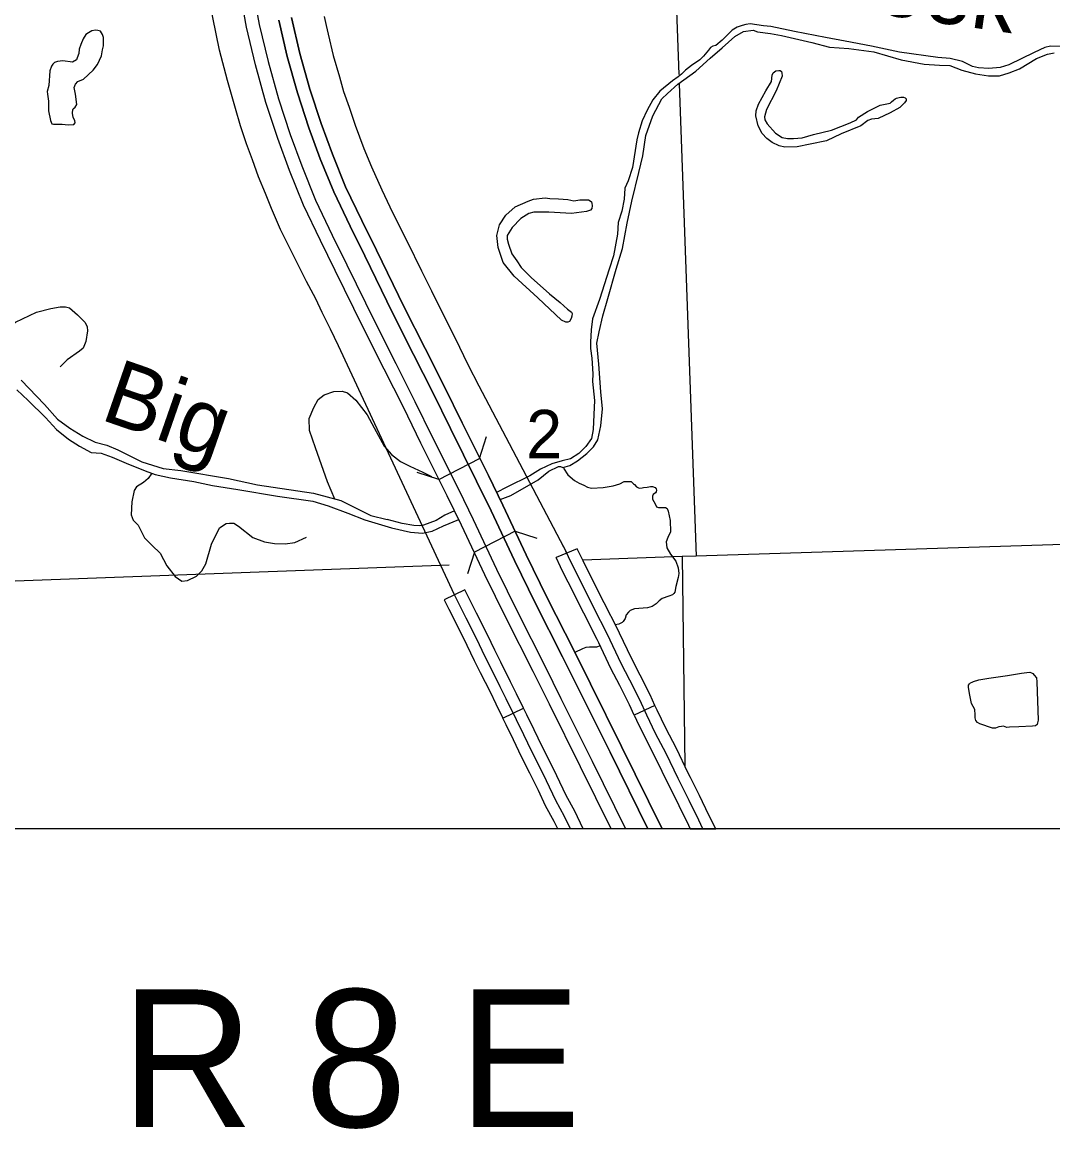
# Model space of a CAD drawing. Extents: x -117616 to 64730, y 54117 to 789866.
# Drawn here: x 62911 to 63045.9, y 54350 to 54494.9 of the extents above; entities that cross this region are included whole.
import ezdxf

# ---------------------------------------------------------------- set-up
doc = ezdxf.new("R2010")
doc.units = 0
for name, color, linetype in [('19', 7, 'Continuous'), ('27', 7, 'Continuous'), ('35', 7, 'Continuous'), ('36', 7, 'Continuous'), ('4', 7, 'Continuous'), ('5', 7, 'Continuous'), ('9', 7, 'Continuous'), ('Default', 7, 'Continuous'), ('R_No Plot', 7, 'Continuous')]:
    doc.layers.add(name, color=color, linetype=linetype)

msp = doc.modelspace()

# ---------------------------------------------------------------- linework, layer by layer
at = {"layer": '19'}
for p, q in [((62940.38, 54494.27), (62939.42, 54499.38)), ((62941.1, 54499.66), (62942.04, 54494.62)), ((62946.25, 54495.51), (62947.35, 54490.82)), ((62941.54, 54489.33), (62940.38, 54494.27)), ((62942.04, 54494.62), (62943.19, 54489.75)), ((62945.71, 54490.4), (62944.58, 54495.16)), ((62943.19, 54489.75), (62944.54, 54484.88)), ((62947.03, 54485.64), (62945.71, 54490.4)), ((62947.35, 54490.82), (62948.66, 54486.13)), ((62942.91, 54484.39), (62941.54, 54489.33)), ((62948.53, 54481.08), (62947.03, 54485.64)), ((62948.66, 54486.13), (62950.13, 54481.64)), ((62944.47, 54479.67), (62942.91, 54484.39)), ((62944.54, 54484.88), (62946.07, 54480.22)), ((62950.02, 54477.03), (62948.53, 54481.08)), ((62950.13, 54481.64), (62951.61, 54477.64)), ((62946.01, 54475.48), (62944.47, 54479.67)), ((62946.07, 54480.22), (62947.6, 54476.09)), ((62951.79, 54472.68), (62950.02, 54477.03)), ((62951.61, 54477.64), (62953.34, 54473.37)), ((62947.85, 54470.95), (62946.01, 54475.48)), ((62947.6, 54476.09), (62949.41, 54471.63)), ((62953.93, 54468.19), (62951.79, 54472.68)), ((62953.34, 54473.37), (62955.46, 54468.93)), ((62950.06, 54466.31), (62947.85, 54470.95)), ((62949.41, 54471.63), (62951.59, 54467.05)), ((62955.85, 54464.31), (62953.93, 54468.19)), ((62955.46, 54468.93), (62957.38, 54465.06)), ((62951.59, 54467.05), (62953.52, 54463.16)), ((62951.99, 54462.41), (62950.06, 54466.31)), ((62957.38, 54465.06), (62961.02, 54457.6)), ((62959.49, 54456.85), (62955.85, 54464.31)), ((62955.64, 54454.93), (62951.99, 54462.41)), ((62953.52, 54463.16), (62957.17, 54455.69)), ((62962.24, 54451.42), (62959.49, 54456.85)), ((62961.02, 54457.6), (62963.76, 54452.19)), ((62958.4, 54449.48), (62955.64, 54454.93)), ((62957.17, 54455.69), (62959.92, 54450.25)), ((62963.76, 54452.19), (62966.28, 54447.18)), ((62964.75, 54446.42), (62962.24, 54451.42)), ((62960.9, 54444.51), (62958.4, 54449.48)), ((62959.92, 54450.25), (62962.42, 54445.27)), ((62967.06, 54441.71), (62964.75, 54446.42)), ((62966.28, 54447.18), (62968.58, 54442.46)), ((62962.42, 54445.27), (62964.72, 54440.56)), ((62963.2, 54439.81), (62960.9, 54444.51)), ((62968.58, 54442.46), (62972.02, 54435.58)), ((62964.72, 54440.56), (62968.16, 54433.68)), ((62970.49, 54434.83), (62967.06, 54441.71)), ((62966.64, 54432.93), (62963.2, 54439.81)), ((62972.39, 54430.93), (62970.49, 54434.83)), ((62972.02, 54435.58), (62973.92, 54431.67)), ((62968.16, 54433.68), (62970.04, 54429.81)), ((62968.51, 54429.08), (62966.64, 54432.93)), ((62975.45, 54424.43), (62972.39, 54430.93)), ((62973.92, 54431.67), (62976.98, 54425.17)), ((62971.57, 54422.57), (62968.51, 54429.08)), ((62970.04, 54429.81), (62973.1, 54423.31)), ((62976.98, 54425.17), (62979.71, 54419.57)), ((62973.1, 54423.31), (62975.86, 54417.65)), ((62978.19, 54418.81), (62975.45, 54424.43)), ((62974.34, 54416.89), (62971.57, 54422.57)), ((62981.73, 54411.83), (62978.19, 54418.81)), ((62979.71, 54419.57), (62983.24, 54412.6)), ((62975.86, 54417.65), (62979.4, 54410.66)), ((62977.88, 54409.9), (62974.34, 54416.89)), ((62983.86, 54407.56), (62981.73, 54411.83)), ((62983.24, 54412.6), (62985.38, 54408.32)), ((62979.4, 54410.66), (62981.53, 54406.4)), ((62980.01, 54405.64), (62977.88, 54409.9)), ((62987.95, 54399.34), (62983.86, 54407.56)), ((62985.38, 54408.32), (62989.47, 54400.09)), ((62984.1, 54397.43), (62980.01, 54405.64)), ((62981.53, 54406.4), (62985.62, 54398.19)), ((62989.47, 54400.09), (62994.78, 54389.3)), ((62992.89, 54389.3), (62987.95, 54399.34)), ((62988.1, 54389.3), (62984.1, 54397.43)), ((62985.62, 54398.19), (62989.99, 54389.3)), ((62989.99, 54389.3), (62988.1, 54389.3)), ((62994.78, 54389.3), (62992.89, 54389.3))]:
    msp.add_line(p, q, dxfattribs=at)
for points in [[(62994.78, 54389.3), (62989.47, 54400.09), (62985.38, 54408.32), (62983.24, 54412.6), (62979.71, 54419.57), (62976.98, 54425.17), (62973.92, 54431.67), (62972.02, 54435.58), (62968.58, 54442.46), (62966.28, 54447.18), (62963.76, 54452.19), (62961.02, 54457.6), (62957.38, 54465.06), (62955.46, 54468.93), (62953.34, 54473.37), (62951.61, 54477.64), (62950.13, 54481.64), (62948.66, 54486.13), (62947.35, 54490.82), (62946.25, 54495.51)], [(62944.58, 54495.16), (62945.71, 54490.4), (62947.03, 54485.64), (62948.53, 54481.08), (62950.02, 54477.03), (62951.79, 54472.68), (62953.93, 54468.19), (62955.85, 54464.31), (62959.49, 54456.85), (62962.24, 54451.42), (62964.75, 54446.42), (62967.06, 54441.71), (62970.49, 54434.83), (62972.39, 54430.93), (62975.45, 54424.43), (62978.19, 54418.81), (62981.73, 54411.83), (62983.86, 54407.56), (62987.95, 54399.34), (62992.89, 54389.3)]]:
    msp.add_lwpolyline(points, dxfattribs=at)
at = {"layer": '27'}
for p, q in [((62983.66, 54425.98), (62980.89, 54424.82)), ((62973.92, 54403.81), (62976.61, 54405.13)), ((62976.61, 54405.13), (62976.61, 54405.13)), ((62993.83, 54405.45), (62991.1, 54404.2)), ((62991.1, 54404.2), (62991.39, 54403.56)), ((62994.1, 54404.85), (62993.83, 54405.45)), ((62995.25, 54402.49), (62994.1, 54404.85)), ((62991.39, 54403.56), (62992.57, 54401.15)), ((62996.63, 54399.83), (62995.25, 54402.49)), ((62992.57, 54401.15), (62993.95, 54398.49)), ((62993.95, 54398.49), (62995.5, 54395.27)), ((62998.19, 54396.59), (62996.63, 54399.83)), ((62998.48, 54396.02), (62998.19, 54396.59)), ((62999.65, 54393.69), (62998.48, 54396.02)), ((62995.5, 54395.27), (62995.8, 54394.68)), ((62995.8, 54394.68), (62996.95, 54392.36)), ((63000.9, 54391.09), (62999.65, 54393.69)), ((62996.95, 54392.36), (62998.21, 54389.78)), ((62998.21, 54389.78), (62998.44, 54389.3)), ((63001.79, 54389.3), (63000.9, 54391.09)), ((62998.44, 54389.3), (63001.79, 54389.3))]:
    msp.add_line(p, q, dxfattribs=at)
for points in [[(62967.58, 54419.93), (62952.43, 54452.53), (62951.35, 54454.72), (62950.29, 54456.91), (62949.43, 54458.71), (62948.24, 54460.96), (62946.16, 54465.07), (62944.83, 54467.77), (62943.65, 54470.52), (62942.84, 54472.47), (62941.96, 54474.65), (62941.14, 54476.88), (62940.37, 54479), (62939.59, 54481.35), (62938.91, 54483.62), (62937.88, 54487.27), (62936.85, 54491.26), (62935.97, 54495.52), (62935.14, 54500.51), (62934.92, 54502.07), (62934.53, 54505.31), (62934.19, 54509.16), (62934.16, 54509.68)], [(62950.53, 54495.63), (62950.79, 54494.48), (62951.04, 54493.35), (62951.69, 54490.53), (62952.53, 54487.74), (62953.08, 54485.83), (62953.8, 54483.8), (62954.59, 54481.44), (62955.74, 54478.38), (62956.72, 54475.98), (62958.06, 54472.98), (62959.13, 54470.72), (62960.57, 54467.82), (62961.4, 54466.2), (62963.28, 54462.36), (62964.58, 54459.74), (62966.36, 54456.14), (62967.68, 54453.55), (62969.33, 54450.12), (62970.77, 54447.3), (62982.29, 54425.4)], [(63000.11, 54389.3), (62999.56, 54390.44), (62998.3, 54393.03), (62996.85, 54395.93), (62995.29, 54399.16), (62993.91, 54401.82), (62992.75, 54404.2), (62991.83, 54406.2), (62990.55, 54408.76), (62989.41, 54410.98), (62987.61, 54414.76), (62985.84, 54418.24), (62983.81, 54422.3), (62982.82, 54424.26), (62981.85, 54426.3)], [(62984.42, 54424.42), (62984.16, 54424.92), (62983.66, 54425.98)], [(62981.74, 54423.06), (62981.47, 54423.6), (62980.89, 54424.82)], [(62986.47, 54413.66), (62986.26, 54414.1), (62984.5, 54417.57), (62982.47, 54421.62), (62981.74, 54423.06)], [(62989.18, 54414.95), (62988.95, 54415.42), (62987.18, 54418.92), (62985.15, 54422.97), (62984.42, 54424.42)], [(62971.9, 54414.7), (62970.47, 54417.55), (62969.55, 54419.4), (62968.96, 54420.61), (62966.26, 54419.29)], [(62966.26, 54419.29), (62966.86, 54418.07), (62967.79, 54416.21), (62969.21, 54413.37)], [(62982.78, 54389.3), (62981.98, 54390.95), (62980.86, 54393.02), (62979.62, 54395.62), (62978.81, 54397.29), (62977.72, 54399.43), (62976.65, 54401.61), (62975.69, 54403.6), (62974.35, 54406.33), (62973.59, 54407.91), (62972.3, 54410.46), (62971.52, 54412.03), (62970.55, 54414.04), (62969.13, 54416.88), (62968.2, 54418.73), (62967.61, 54419.95)], [(62976.61, 54405.13), (62975.7, 54406.98), (62974.94, 54408.58), (62973.64, 54411.14), (62972.87, 54412.69), (62971.9, 54414.7)], [(62993.83, 54405.45), (62993.18, 54406.85), (62991.89, 54409.44), (62990.75, 54411.65), (62989.18, 54414.95)], [(62969.21, 54413.37), (62970.17, 54411.37), (62970.96, 54409.79), (62972.25, 54407.25), (62973, 54405.67), (62973.92, 54403.81)], [(62991.1, 54404.2), (62990.48, 54405.55), (62989.21, 54408.08), (62988.06, 54410.31), (62986.47, 54413.66)], [(62980.97, 54396.27), (62980.97, 54396.27), (62980.16, 54397.95), (62979.07, 54400.1), (62978, 54402.26), (62977.04, 54404.26), (62976.61, 54405.13)], [(62978.57, 54394.35), (62978.27, 54394.97), (62977.47, 54396.62), (62976.38, 54398.76), (62975.31, 54400.95), (62974.34, 54402.94), (62973.92, 54403.81)], [(62984.44, 54389.3), (62983.32, 54391.63), (62982.2, 54393.7), (62980.97, 54396.27)], [(62981.11, 54389.3), (62980.65, 54390.26), (62979.52, 54392.34), (62978.57, 54394.35)]]:
    msp.add_lwpolyline(points, dxfattribs=at)
at = {"layer": '35'}
for points in [[(63046.88, 54491.74), (63045.6, 54491.76), (63044.84, 54491.6), (63043.47, 54490.96), (63040.13, 54489.33), (63038.99, 54488.99), (63037.54, 54488.85), (63036.17, 54488.91), (63035.4, 54489.09), (63034.09, 54489.74), (63032.48, 54490.17), (63030.83, 54490.27), (63025.83, 54490.97), (63022.16, 54491.78), (63018.71, 54492.43), (63016.14, 54492.9), (63012.09, 54493.7), (63009.01, 54494.35), (63008.05, 54494.45), (63007.17, 54494.57), (63006.27, 54494.67), (63005.72, 54494.61), (63005.25, 54494.49), (63004.6, 54494.25), (63003.95, 54493.88), (63002.62, 54492.55), (63001.79, 54491.84), (63001.4, 54491.76), (63001.11, 54491.6), (63000.83, 54491.23), (63000.2, 54490.48), (62999.68, 54489.97), (62998.6, 54489.23), (62997.81, 54488.62), (62997.32, 54488.09), (62996.87, 54487.75), (62996.14, 54487.22), (62994.46, 54485.87), (62993.53, 54484.75), (62992.81, 54483.38), (62992.16, 54482), (62991.69, 54480.41), (62991.47, 54479.49), (62990.87, 54475.87), (62990.3, 54474.15), (62989.9, 54473.2), (62989.79, 54471.75), (62989.51, 54470.18), (62989.02, 54468.69), (62988.94, 54467.14), (62988.41, 54464.33), (62987.84, 54462.58), (62986.55, 54458.6), (62985.67, 54456.06), (62985.49, 54454.65), (62985.37, 54453.02), (62985.39, 54452.19), (62985.57, 54450.92), (62985.69, 54448.86), (62985.65, 54447.87), (62985.92, 54445.38), (62985.82, 54443.57), (62985.76, 54441.57), (62985.51, 54440.41), (62984.8, 54439.35), (62983.88, 54438.45), (62982.76, 54437.74), (62981.68, 54437.47), (62980.33, 54437.09), (62978.84, 54436.41), (62977.45, 54435.54), (62974.42, 54434.03), (62973.1, 54433.36)], [(62917.59, 54489.68), (62916.34, 54489.86), (62915.64, 54489.78), (62915.24, 54489.62), (62915, 54489.41), (62914.84, 54489.14), (62914.65, 54488.53), (62914.49, 54486.63), (62914.28, 54485.85), (62914.33, 54485.48), (62914.44, 54484.55), (62914.44, 54483.32), (62914.73, 54482.03), (62914.9, 54481.61), (62915.11, 54481.55), (62915.43, 54481.55), (62916.23, 54481.55), (62917.03, 54481.47), (62917.75, 54481.53), (62917.96, 54481.74), (62917.91, 54482.03), (62917.7, 54482.44), (62917.59, 54483), (62917.62, 54483.48), (62917.7, 54483.58), (62917.94, 54483.8), (62918.18, 54484.15), (62917.99, 54485.48), (62917.83, 54486.34), (62917.98, 54486.79), (62918.31, 54487.14), (62919.03, 54487.46), (62920.31, 54488.63), (62920.87, 54489.38), (62921.38, 54490.5), (62921.51, 54491.28), (62921.67, 54491.79), (62921.67, 54492.35), (62921.65, 54492.88), (62921.54, 54493.31), (62921.27, 54493.71), (62920.93, 54493.82), (62920.61, 54493.87), (62920.13, 54493.79), (62919.67, 54493.52), (62919.35, 54493.28), (62919.01, 54492.72), (62918.69, 54492), (62918.47, 54491.39), (62918.44, 54490.82), (62918.2, 54490.24), (62918.12, 54490), (62917.59, 54489.68)], [(62999.16, 54488.51), (63001.04, 54490.19), (63002.63, 54491.53), (63004.28, 54493.05), (63005.42, 54493.69), (63006.66, 54493.87), (63007.25, 54493.64), (63008.94, 54493.41), (63010.41, 54493.15), (63014.37, 54492.24), (63016.68, 54491.63), (63019.21, 54491.45), (63022.46, 54491.02), (63026.03, 54489.96), (63029.05, 54489.43), (63031.07, 54489.3), (63032.42, 54489.22), (63033.99, 54488.64), (63035.76, 54488.13), (63037.49, 54487.88), (63038.93, 54487.9), (63040.2, 54488.28), (63041.54, 54488.79), (63043.75, 54490.14), (63045.19, 54490.72), (63046.08, 54490.9)], [(62973.59, 54432.41), (62974.98, 54432.94), (62978.55, 54435), (62979.92, 54436.12), (62981.19, 54436.73), (62981.47, 54436.73), (62981.77, 54436.62), (62982.68, 54436.9), (62983.67, 54437.51), (62984.91, 54438.45), (62985.78, 54439.31), (62986.36, 54440.23), (62986.74, 54442.05), (62986.94, 54444.29), (62986.74, 54446.54), (62986.49, 54450.15), (62986.23, 54452.89), (62986.51, 54454.36), (62986.99, 54456.47), (62987.68, 54458.72), (62988.74, 54462.58), (62989.6, 54465.3), (62990.19, 54468.62), (62990.82, 54471.46), (62991.71, 54475.22), (62992.24, 54477.4), (62992.65, 54480.06), (62993.56, 54482.63), (62994.72, 54484.88), (62995.46, 54485.57), (62996.8, 54486.81), (62999.16, 54488.51)], [(63009.18, 54487.95), (63009.3, 54488.29), (63009.64, 54488.53), (63010.03, 54488.6), (63010.22, 54488.6), (63010.41, 54488.46), (63010.43, 54488.26), (63010.48, 54487.83), (63009.71, 54485.9), (63008.44, 54483.47), (63008.15, 54482.53), (63008.2, 54482.14), (63008.51, 54481.61), (63009.59, 54480.38), (63010.46, 54479.8), (63011.18, 54479.68), (63011.98, 54479.68), (63013.08, 54479.76), (63014.58, 54480.19), (63016.94, 54480.79), (63019.37, 54481.73), (63020.21, 54482.12), (63020.45, 54482.48), (63021.63, 54483.2), (63023.32, 54484.05), (63024.18, 54484.24), (63024.59, 54484.31), (63024.78, 54484.48), (63025.05, 54484.7), (63025.27, 54484.89), (63025.46, 54484.96), (63025.77, 54485.06), (63025.99, 54485.08), (63026.37, 54485.08), (63026.57, 54485.01), (63026.71, 54484.86), (63026.69, 54484.67), (63026.49, 54484.33), (63025.87, 54483.76), (63024.62, 54483.06), (63023.03, 54482.29), (63022.18, 54482.21), (63021.68, 54482.02), (63020.76, 54481.35), (63018.21, 54480.29), (63016.26, 54479.39), (63014.12, 54478.94), (63012.43, 54478.6), (63010.84, 54478.53), (63010.07, 54478.7), (63009.18, 54479.15), (63008.48, 54479.68), (63007.86, 54480.33), (63007.35, 54481.35), (63007.04, 54482.67), (63007.06, 54483.3), (63007.4, 54484.19), (63008.36, 54485.9), (63009.06, 54487.15), (63009.18, 54487.95)], [(62979.47, 54471.9), (62980.06, 54471.84), (62981.19, 54471.77), (62982.43, 54471.69), (62983.22, 54471.52), (62984.01, 54471.64), (62984.65, 54471.64), (62985.13, 54471.64), (62985.34, 54471.54), (62985.53, 54471.4), (62985.58, 54471.21), (62985.6, 54470.85), (62985.55, 54470.52), (62985.39, 54470.28), (62984.86, 54470.11), (62982.91, 54469.87), (62979.94, 54470.04), (62977.99, 54470.06), (62977.33, 54469.87), (62976.28, 54469.23), (62975.14, 54468.02), (62974.5, 54466.99), (62974.5, 54466.52), (62974.66, 54465.83), (62975.11, 54464.59), (62975.73, 54463.66), (62976.3, 54462.78), (62977.61, 54461.49), (62980.01, 54459.33), (62981.42, 54458.21), (62982.39, 54457.35), (62982.91, 54456.97), (62982.99, 54456.78), (62982.96, 54456.42), (62982.87, 54456.14), (62982.63, 54455.71), (62982.44, 54455.66), (62982.15, 54455.66), (62981.61, 54455.92), (62978.49, 54458.83), (62975.4, 54461.66), (62973.95, 54463.47), (62973.31, 54465.42), (62973.14, 54466.99), (62973.47, 54468.4), (62974.31, 54469.64), (62975.54, 54470.75), (62977.25, 54471.47), (62977.94, 54471.73), (62979.47, 54471.9)], [(62906.34, 54453.07), (62910.12, 54455.66), (62912.88, 54456.95), (62914.75, 54457.41), (62915.96, 54457.66), (62916.7, 54457.66), (62917.2, 54457.51), (62918.27, 54456.6), (62919.25, 54455.61), (62919.51, 54455.05), (62919.56, 54454.52), (62919.33, 54453.13), (62918.97, 54452.24), (62918.49, 54451.84), (62916.9, 54450.7), (62915.99, 54449.78)], [(62910.89, 54448.05), (62913.94, 54444.86), (62915.65, 54442.93), (62917.25, 54441.75), (62918.96, 54440.7), (62920.56, 54439.94), (62922.08, 54439.55), (62923.54, 54438.93), (62926.66, 54437.38), (62929.48, 54436.47), (62931.76, 54436.21), (62938.02, 54435.17), (62941.83, 54434.35), (62949.13, 54433.25), (62952.7, 54432.28), (62956.62, 54430.33), (62958.8, 54429.79)], [(62910.29, 54446.8), (62911.81, 54445.38), (62914.06, 54443.14), (62915.51, 54441.57), (62917.08, 54440.33), (62918.52, 54439.39), (62920.02, 54438.6), (62921.34, 54438.5), (62922.78, 54437.99), (62924.61, 54437.18), (62927.12, 54436.17), (62928.41, 54435.68), (62930.44, 54435.28), (62933.48, 54434.8), (62935.91, 54434.26), (62939.23, 54433.73), (62944.41, 54432.87), (62949.07, 54432.23), (62951.07, 54431.6), (62953.61, 54430.66), (62955.84, 54429.75), (62959.34, 54428.71), (62961.82, 54428.15), (62963.39, 54428.02), (62964.68, 54428.3), (62966.16, 54428.96), (62968.15, 54429.82)], [(62951.93, 54432.49), (62950.95, 54434.74), (62949.4, 54439.21), (62948.6, 54441.46), (62948.58, 54443.03), (62949.19, 54444.49), (62949.73, 54445.5), (62950.52, 54446.13), (62951.81, 54446.58), (62952.87, 54446.6), (62953.6, 54446.37), (62954.68, 54445.41), (62956.18, 54443.53), (62957.07, 54441.81), (62958.38, 54439.42), (62959.35, 54438.31), (62960.54, 54437.4), (62961.74, 54436.81), (62963.43, 54436.01), (62964.58, 54435.43)], [(62981.86, 54436.51), (62982.44, 54435.66), (62983.31, 54434.93), (62983.89, 54434.56), (62984.54, 54434.29), (62984.99, 54434.06), (62985.52, 54433.9), (62987.07, 54433.98), (62988.36, 54434.22), (62989.25, 54434.5), (62989.81, 54434.79), (62990.09, 54434.79), (62990.41, 54434.79), (62990.73, 54434.77), (62991.02, 54434.5), (62991.15, 54434.4), (62991.41, 54434.08), (62991.75, 54433.93), (62992.17, 54433.95), (62992.33, 54434), (62992.8, 54434.03), (62993.23, 54434.11), (62993.51, 54434.11), (62993.86, 54434), (62993.99, 54433.82), (62994.01, 54433.64), (62993.99, 54433.43), (62993.88, 54433.29), (62993.59, 54433.08), (62993.49, 54432.85), (62993.51, 54432.48), (62993.86, 54431.87), (62994.04, 54431.45), (62994.28, 54431.4), (62994.94, 54431.4), (62995.2, 54431.4), (62995.44, 54431.24), (62995.57, 54430.92), (62995.8, 54429.69), (62995.86, 54428.21), (62995.51, 54427.47), (62995.28, 54426.87), (62995.36, 54426.1), (62995.86, 54425.29), (62996.54, 54424.37), (62996.86, 54423.47), (62996.96, 54422.73), (62996.88, 54422.21), (62996.57, 54421.02), (62996.41, 54420.31), (62996.3, 54420.13), (62996.12, 54419.97), (62995.65, 54419.76), (62994.78, 54419.47), (62994.36, 54419.18), (62993.99, 54418.76), (62993.46, 54418.42), (62992.83, 54418.26), (62991.17, 54418.1), (62990.59, 54417.92), (62990.36, 54417.7), (62990.07, 54417.34), (62989.91, 54416.86), (62989.67, 54416.47), (62989.54, 54416.34), (62989.09, 54416.12), (62988.64, 54416.04)], [(62927.97, 54435.89), (62927.5, 54435.17), (62926.89, 54434.66), (62925.99, 54434.08), (62925.66, 54433.61), (62925.37, 54432.13), (62925.26, 54430.4), (62925.52, 54429.71), (62926.17, 54429.06), (62927.03, 54427.43), (62928.01, 54426.39), (62929.09, 54425.41), (62929.96, 54423.75), (62931.04, 54422.34), (62931.91, 54421.76), (62932.63, 54421.83), (62933.82, 54422.41), (62934.54, 54423.1), (62935.05, 54424), (62935.8, 54426.6), (62936.82, 54428.7), (62937.72, 54429.28), (62938.15, 54429.35), (62938.73, 54429.35), (62939.31, 54428.95), (62941.18, 54427.47), (62942.74, 54426.89), (62944.03, 54426.67), (62945.41, 54426.64), (62946.71, 54426.78), (62948.22, 54427.51)], [(62967.6, 54430.95), (62966.34, 54430.36), (62965.18, 54429.69), (62963.52, 54429.06), (62963.06, 54428.98), (62962.26, 54429.02), (62960.75, 54429.28), (62958.8, 54429.79)], [(62986.65, 54413.27), (62986.17, 54413.1), (62985.57, 54413.1), (62985.25, 54413.1), (62984.78, 54413.04), (62984.33, 54412.86), (62983.35, 54412.39)], [(63036.22, 54408.81), (63037.53, 54409.05), (63039.96, 54409.4), (63041.8, 54409.69), (63042.48, 54409.8), (63042.89, 54409.81), (63043.1, 54409.76), (63043.29, 54409.64), (63043.46, 54409.45), (63043.75, 54409.09), (63043.82, 54408.57), (63043.96, 54403.55), (63043.91, 54403.19), (63043.84, 54402.97), (63043.63, 54402.81), (63043.25, 54402.74), (63041.43, 54402.66), (63040.25, 54402.64), (63039.89, 54402.59), (63039.65, 54402.66), (63039.44, 54402.74), (63039.19, 54402.73), (63038.84, 54402.69), (63038.38, 54402.49), (63038, 54402.49), (63036.34, 54403.05), (63036.03, 54403.26), (63035.81, 54403.52), (63035.72, 54403.86), (63035.72, 54404.24), (63035.69, 54404.93), (63035.24, 54405.73), (63034.98, 54407.05), (63034.86, 54407.86), (63034.86, 54408.11), (63034.98, 54408.3), (63035.12, 54408.42), (63035.36, 54408.54), (63035.52, 54408.62), (63036.22, 54408.81)]]:
    msp.add_lwpolyline(points, dxfattribs=at)
at = {"layer": '36'}
for p, q in [((62970.88, 54437.81), (62971.8, 54440.67)), ((62965.55, 54435.06), (62970.88, 54437.81)), ((62965.55, 54435.06), (62962.69, 54435.97)), ((62975.52, 54428.29), (62970.19, 54425.54)), ((62975.52, 54428.29), (62978.38, 54427.38)), ((62970.19, 54425.54), (62969.28, 54422.68))]:
    msp.add_line(p, q, dxfattribs=at)
at = {"layer": '4'}
for points in [[(63114.2, 54428.54), (63104.13, 54428.35), (63103.57, 54428.33), (62999.2, 54425.01), (62997.38, 54424.95), (62984.39, 54424.47)], [(62966.89, 54423.83), (62892.31, 54421.09)]]:
    msp.add_lwpolyline(points, dxfattribs=at)
at = {"layer": '5'}
for points in [[(62995.48, 54528.73), (62996.94, 54488.07)], [(62996.98, 54486.85), (62999.2, 54425.01)], [(62997.38, 54424.95), (62997.73, 54397.55)]]:
    msp.add_lwpolyline(points, dxfattribs=at)
at = {"layer": 'R_No Plot'}
msp.add_lwpolyline([(62347.42, 55314.94), (63854.85, 55314.94), (63854.85, 54389.3), (62347.42, 54389.3)], close=True, dxfattribs=at)

# ---------------------------------------------------------------- texts
at = {"layer": '35'}
for s, rotation, p in [('Creek', 351.6271, (63010.7, 54497.83)), ('Big', 340.8059, (62921.04, 54442.97))]:
    msp.add_text(s, height=8.448, rotation=rotation, dxfattribs=at).set_placement(p)
at = {"layer": '9'}
msp.add_text('2', height=6.34, dxfattribs=at).set_placement((62976.97, 54437.82))
at = {"layer": 'Default'}
msp.add_text('R 8 E', height=18, dxfattribs=at).set_placement((62923.92, 54350.3))

doc.saveas('drawing.dxf')
